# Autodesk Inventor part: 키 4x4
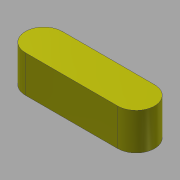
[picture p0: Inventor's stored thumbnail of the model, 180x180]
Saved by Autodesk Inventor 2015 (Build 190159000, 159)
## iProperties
Created: 2016-04
Part Number: 키 4x4
Document SubType Name: Modeling
Designer: mdu
Density: 7.86 g/cm^3
Mass: 1.65269 g
Surface Area: 2.35398 cm^2
Volume: 0.210265 cm^3
Material: 강철, 연강
Appearance: 강철 - 광택
Author: mdu
Revision Number: 1
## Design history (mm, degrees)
sketch "스케치1"
  geometry: L1 (-5, -2)-(5, -2); L2 (5, 2)-(-5, 2); A1 r 2 centre (5, 0) between (5, -2) and (5, 2); A2 r 2 centre (-5, 0) between (-5, 2) and (-5, -2); 2 further points
  constraints: 4 end point, 4 point on circle, 4 tangent, 2 centre point, 1 horizontal, 1 horizontal alignment, 1 midpoint, 1 parallel, 1 vertical alignment
  dimensions: "d0" = 4 distance between parallel lines of L1 L2; "d1" = 14 dimension on A1 A2
extrude "돌출1" new body sketch "스케치1" stored distance "d2" = 4; taper "d3" = 0 deg
node "솔리드1"
